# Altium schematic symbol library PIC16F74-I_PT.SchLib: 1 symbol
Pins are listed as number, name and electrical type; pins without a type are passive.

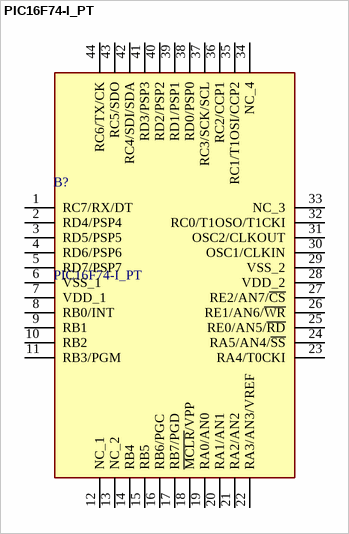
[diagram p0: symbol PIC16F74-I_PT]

## PIC16F74-I_PT
designator B?
Microcontroller,PIC16F74-I/PT 20MHz PIC16F74-I/PT, 8 bit PIC Microcontroller 20MHz 4K x 14 words Flash, 192 B RAM, I2C 44-Pin TQFP; Manufacturer_Name: Microchip; Geometry.Height: 1.2mm
footprint QFP80P1200X1200X120-44N
pins: 1 RC7/RX/DT, 2 RD4/PSP4, 3 RD5/PSP5, 4 RD6/PSP6, 5 RD7/PSP7, 6 VSS_1, 7 VDD_1, 8 RB0/INT, 9 RB1, 10 RB2, 11 RB3/PGM, 12 NC_1, 13 NC_2, 14 RB4, 15 RB5, 16 RB6/PGC, 17 RB7/PGD, 18 ~{MCLR}/VPP, 19 RA0/AN0, 20 RA1/AN1, 21 RA2/AN2, 22 RA3/AN3/VREF, 23 RA4/T0CKI, 24 RA5/AN4/~{SS}, 25 RE0/AN5/~{RD}, 26 RE1/AN6/~{WR}, 27 RE2/AN7/~{CS}, 28 VDD_2, 29 VSS_2, 30 OSC1/CLKIN, 31 OSC2/CLKOUT, 32 RC0/T1OSO/T1CKI, 33 NC_3, 34 NC_4, 35 RC1/T1OSI/CCP2, 36 RC2/CCP1, 37 RC3/SCK/SCL, 38 RD0/PSP0, 39 RD1/PSP1, 40 RD2/PSP2, 41 RD3/PSP3, 42 RC4/SDI/SDA, 43 RC5/SDO, 44 RC6/TX/CK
